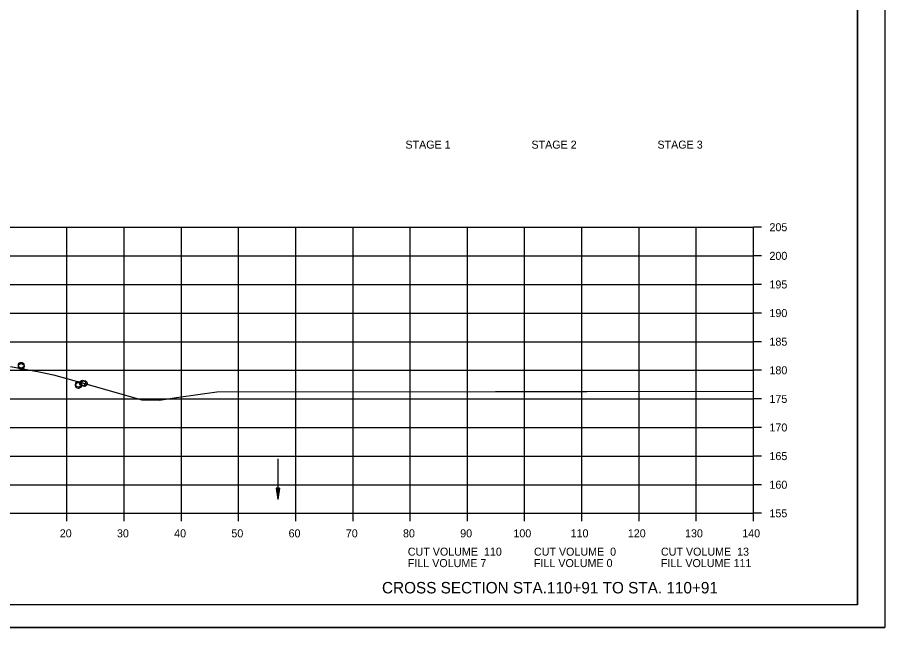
# Model space of a CAD drawing. Extents: x 1372132 to 1372465, y 380083 to 381790.
# Drawn here: x 1372313.3 to 1372464.9, y 381576.9 to 381683.5 of the extents above; entities that cross this region are included whole.
import ezdxf

# ---------------------------------------------------------------- set-up
doc = ezdxf.new("R2010")
doc.units = 0
for name, color, linetype in [('R_Axis', 7, 'Continuous'), ('R_Axis Annot', 7, 'Continuous'), ('R_Border', 7, 'Continuous'), ('R_Dimension', 7, 'Continuous'), ('R_Draft', 7, 'Continuous'), ('R_Exist Surface', 7, 'Continuous'), ('R_Grid', 7, 'Continuous'), ('R_No Plot', 7, 'Continuous')]:
    doc.layers.add(name, color=color, linetype=linetype)

msp = doc.modelspace()

# ---------------------------------------------------------------- linework, layer by layer
at = {"layer": 'R_Axis'}
for p, q in [((1372442.01, 381596.84), (1372442.01, 381646.84)), ((1372443.41, 381646.84), (1372442.01, 381646.84)), ((1372443.41, 381641.84), (1372442.01, 381641.84)), ((1372443.41, 381636.84), (1372442.01, 381636.84)), ((1372443.41, 381631.84), (1372442.01, 381631.84)), ((1372443.41, 381626.84), (1372442.01, 381626.84)), ((1372443.41, 381621.84), (1372442.01, 381621.84)), ((1372443.41, 381616.84), (1372442.01, 381616.84)), ((1372443.41, 381611.84), (1372442.01, 381611.84)), ((1372443.41, 381606.84), (1372442.01, 381606.84)), ((1372443.41, 381601.84), (1372442.01, 381601.84)), ((1372162.01, 381596.84), (1372442.01, 381596.84)), ((1372322.01, 381595.44), (1372322.01, 381596.84)), ((1372332.01, 381595.44), (1372332.01, 381596.84)), ((1372342.01, 381595.44), (1372342.01, 381596.84)), ((1372352.01, 381595.44), (1372352.01, 381596.84)), ((1372362.01, 381595.44), (1372362.01, 381596.84)), ((1372372.01, 381595.44), (1372372.01, 381596.84)), ((1372382.01, 381595.44), (1372382.01, 381596.84)), ((1372392.01, 381595.44), (1372392.01, 381596.84)), ((1372402.01, 381595.44), (1372402.01, 381596.84)), ((1372412.01, 381595.44), (1372412.01, 381596.84)), ((1372422.01, 381595.44), (1372422.01, 381596.84)), ((1372432.01, 381595.44), (1372432.01, 381596.84)), ((1372442.01, 381595.44), (1372442.01, 381596.84)), ((1372443.41, 381596.84), (1372442.01, 381596.84))]:
    msp.add_line(p, q, dxfattribs=at)
at = {"layer": 'R_Border'}
for q in [(1372460.19, 381786.3), (1372144.01, 381580.84)]:
    msp.add_line((1372460.19, 381580.84), q, dxfattribs=at)
at = {"layer": 'R_Dimension'}
for p, q in [((1372358.58, 381601.24), (1372358.88, 381599.24)), ((1372359.18, 381601.24), (1372358.58, 381601.24)), ((1372358.58, 381601.24), (1372358.88, 381599.24)), ((1372359.18, 381601.24), (1372358.58, 381601.24)), ((1372358.63, 381601.24), (1372358.88, 381599.58)), ((1372358.63, 381601.24), (1372358.88, 381599.58)), ((1372358.68, 381601.24), (1372358.88, 381599.92)), ((1372358.68, 381601.24), (1372358.88, 381599.92)), ((1372358.73, 381601.24), (1372358.88, 381600.26)), ((1372358.73, 381601.24), (1372358.88, 381600.26)), ((1372358.78, 381601.24), (1372358.88, 381600.59)), ((1372358.78, 381601.24), (1372358.88, 381600.59)), ((1372358.83, 381601.24), (1372358.88, 381600.93)), ((1372358.83, 381601.24), (1372358.88, 381600.93)), ((1372359.18, 381601.24), (1372358.88, 381599.24)), ((1372358.97, 381601.24), (1372358.88, 381600.59)), ((1372359.07, 381601.24), (1372358.88, 381599.92)), ((1372359.13, 381601.24), (1372358.88, 381599.58)), ((1372359.02, 381601.24), (1372358.88, 381600.26)), ((1372358.92, 381601.24), (1372358.88, 381600.93)), ((1372359.18, 381601.24), (1372358.88, 381599.24)), ((1372358.97, 381601.24), (1372358.88, 381600.59)), ((1372359.07, 381601.24), (1372358.88, 381599.92)), ((1372359.13, 381601.24), (1372358.88, 381599.58)), ((1372359.02, 381601.24), (1372358.88, 381600.26)), ((1372358.92, 381601.24), (1372358.88, 381600.93))]:
    msp.add_line(p, q, dxfattribs=at)
at = {"layer": 'R_Draft'}
msp.add_line((1372358.88, 381606.38), (1372358.88, 381599.24), dxfattribs=at)
at = {"layer": 'R_Exist Surface'}
msp.add_lwpolyline([(1372312.16, 381622.51), (1372317.13, 381621.56), (1372319.66, 381621.07), (1372324.68, 381619.63), (1372335.07, 381616.68), (1372336.09, 381616.66), (1372338.1, 381616.62), (1372341.55, 381617.12), (1372348.23, 381618.08), (1372396.93, 381618.14), (1372412.9, 381618.15), (1372442.01, 381618.21)], dxfattribs=at)
at = {"layer": 'R_Grid'}
for p, q in [((1372162.01, 381646.84), (1372442.01, 381646.84)), ((1372322.01, 381596.84), (1372322.01, 381646.84)), ((1372332.01, 381596.84), (1372332.01, 381646.84)), ((1372342.01, 381596.84), (1372342.01, 381646.84)), ((1372352.01, 381596.84), (1372352.01, 381646.84)), ((1372362.01, 381596.84), (1372362.01, 381646.84)), ((1372372.01, 381596.84), (1372372.01, 381646.84)), ((1372382.01, 381596.84), (1372382.01, 381646.84)), ((1372392.01, 381596.84), (1372392.01, 381646.84)), ((1372402.01, 381596.84), (1372402.01, 381646.84)), ((1372412.01, 381596.84), (1372412.01, 381646.84)), ((1372422.01, 381596.84), (1372422.01, 381646.84)), ((1372432.01, 381596.84), (1372432.01, 381646.84)), ((1372442.01, 381596.84), (1372442.01, 381646.84)), ((1372162.01, 381641.84), (1372442.01, 381641.84)), ((1372162.01, 381636.84), (1372442.01, 381636.84)), ((1372162.01, 381631.84), (1372442.01, 381631.84)), ((1372162.01, 381626.84), (1372442.01, 381626.84)), ((1372162.01, 381621.84), (1372442.01, 381621.84)), ((1372162.01, 381616.84), (1372442.01, 381616.84)), ((1372162.01, 381611.84), (1372442.01, 381611.84)), ((1372162.01, 381606.84), (1372442.01, 381606.84)), ((1372162.01, 381601.84), (1372442.01, 381601.84)), ((1372162.01, 381596.84), (1372442.01, 381596.84))]:
    msp.add_line(p, q, dxfattribs=at)
at = {"layer": 'R_No Plot'}
msp.add_line((1372131.61, 381576.86), (1372464.95, 381576.86), dxfattribs=at)
for points in [[(1372131.61, 381790.19), (1372464.95, 381790.19), (1372464.95, 381576.86), (1372131.61, 381576.86)], [(1372377.93, 381786.3), (1372377.93, 381776.42), (1372413.67, 381776.42), (1372413.67, 381773.5), (1372436.87, 381773.5), (1372436.87, 381749.17), (1372460.19, 381749.17), (1372460.19, 381580.84), (1372144.01, 381580.84), (1372144.01, 381786.3)]]:
    msp.add_lwpolyline(points, close=True, dxfattribs=at)
for centre in [(1372314.01, 381622.71), (1372314.01, 381622.51), (1372324.01, 381619.38), (1372324.73, 381619.61), (1372325.05, 381619.52), (1372324.01, 381619.18)]:
    msp.add_circle(centre, 0.5, dxfattribs=at)

# ---------------------------------------------------------------- texts
at = {"layer": 'R_Axis Annot'}
for s, p in [('STAGE 1', (1372381.17, 381660.58)), ('STAGE 2', (1372403.2, 381660.58)), ('STAGE 3', (1372425.23, 381660.58)), ('205', (1372444.81, 381646.14)), ('200', (1372444.81, 381641.14)), ('195', (1372444.81, 381636.14)), ('190', (1372444.81, 381631.14)), ('185', (1372444.81, 381626.14)), ('180', (1372444.81, 381621.14)), ('175', (1372444.81, 381616.14)), ('170', (1372444.81, 381611.14)), ('165', (1372444.81, 381606.14)), ('160', (1372444.81, 381601.14)), ('155', (1372444.81, 381596.14)), ('20', (1372320.75, 381592.64)), ('30', (1372330.75, 381592.64)), ('40', (1372340.75, 381592.64)), ('50', (1372350.75, 381592.64)), ('60', (1372360.75, 381592.64)), ('70', (1372370.75, 381592.64)), ('80', (1372380.75, 381592.64)), ('90', (1372390.75, 381592.64)), ('100', (1372400.05, 381592.64)), ('110', (1372410.05, 381592.64)), ('120', (1372420.05, 381592.64)), ('130', (1372430.05, 381592.64)), ('140', (1372440.05, 381592.64)), ('CUT VOLUME  110', (1372381.59, 381589.44)), ('CUT VOLUME  0', (1372403.64, 381589.44)), ('CUT VOLUME  13', (1372425.84, 381589.44)), ('FILL VOLUME 7', (1372381.59, 381587.44)), ('FILL VOLUME 0', (1372403.64, 381587.44)), ('FILL VOLUME 111', (1372425.84, 381587.44))]:
    msp.add_text(s, height=1.4, dxfattribs=at).set_placement(p)
at = {"layer": 'R_Draft'}
msp.add_text('CROSS SECTION STA.110+91 TO STA. 110+91', height=2, dxfattribs=at).set_placement((1372377.08, 381582.84))

doc.saveas('drawing.dxf')
